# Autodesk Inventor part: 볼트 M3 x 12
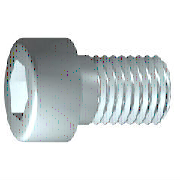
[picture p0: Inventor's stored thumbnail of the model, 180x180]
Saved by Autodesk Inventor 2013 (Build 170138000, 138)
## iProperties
IsCustomPart: 0
Created: 2012-02
Part Number: 볼트 M3 x 12
Material: 강철, 연강
Description: 6각머리 태핑 나사
Document SubType Name: Modeling
Standard: KS B 1003
Designer: mduedu
Standards Organization: KS
Language: ko-KR
Size Designation: M 3 x 12
Categories: <MemberInstance><Categories><Category DisplayName="조임쇠" InternalName="e4da775c-781d-43d5-af7c-5136215cf5a6" Mnemonic="FSTN"><Category DisplayName="볼트" InternalN
Density: 7.86 g/cm^3
Mass: 1.15208 g
Surface Area: 2.207 cm^2
Volume: 0.146575 cm^3
Author: mduedu
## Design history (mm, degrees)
sketch "스케치1"
  geometry: L1 (-0.867, 0)-(12, 0); L2 (12, 0)-(12, 1.5); L3 (12, 1.5)-(1.25, 1.5); L4 (1.25, 1.5)-(0.943, 1.5); L5 (0.943, 1.5)-(0, 1.5); L6 (0, 1.5)-(0, 2.75); L7 (0, 2.75)-(-3, 2.75); L8 (-3, 2.75)-(-3, 1.443); L9 (-3, 1.443)-(-1.7, 1.443); L10 (-1.7, 1.443)-(-0.867, 0); L11 (-6, 0)-(15, 0) reference; L12 (0, -0.55)-(0, 3.3) reference; L13 (1.25, 1.5)-(0, 1.5)
  constraints: 22 end point, 6 parallel, 2 collinear, 2 perpendicular, 1 horizontal, 1 point on line
  dimensions: "d1" = 10.75 distance from line of L3.end L2 (= GEL); "d2" = 0.30683 distance of L4.end L3.end (computed from GAL); "d3" = 3 distance between parallel lines of L8 L6 (= KOH); "d4" = 1.3 distance of L8.end L9.end (= INTI); "d5" = 60 deg angle of L10 L1; "d6" = 3 diameter of L3 L1 (= GD); "d7" = 3 diameter of L5 L1 (= BDM); "d8" = 2.88675 diameter of L9 L1 (= 1.1547 x SW); "d9" = 5.5 diameter of L7 L1 (= KOD); "d26" = 12 distance between parallel lines of L12 L2 (= NLG)
revolve "본체" sketch "스케치1" stored, may be unused: angle "d10" = 90 deg
sketch "스케치2"
  geometry: L1 (0, -3.85)-(0, 3.85) reference; L2 (-3.85, 0)-(3.85, 0) reference; L3 (1.443, 0)-(0.722, -1.25); L4 (0.722, -1.25)-(-0.722, -1.25); L5 (-0.722, -1.25)-(-1.443, 0); L6 (-1.443, 0)-(-0.722, 1.25); L7 (-0.722, 1.25)-(0.722, 1.25); L8 (0.722, 1.25)-(1.443, 0); 2 further points
  constraints: 12 end point, 1 coincident, 1 horizontal alignment, 1 point on line, 12 other
extrude "슬롯" join sketch "스케치2" stored distance "d11" = 10; taper "d12" = 0 deg
workplane "Work Plane1"
fillet "Fillet2" dims "d30" = 0.1 (= R)
body "Solid1"
fillet "모깎기1" dims "d17" = 0.3 (= RR)
feature "스레드" dims "d13" = 10.75 (= GEL), "d14" = 0
chamfer "모따기1" distance "d15" = 0.30673 (= -0.5 x SPD + 0.5 x GD); stored, may be unused: second distance "d16" = 0.30673 (= GUL), angle "d27" = 45 deg
other parameters: "GD" = 3 (= NND) [user parameter; used in 2 equation terms], "NLG" = 12 [user parameter; used in 1 equation term], "GEL" = 10.75 [user parameter; used in 2 equation terms], "KOD" = 5.5 [user parameter; used in 1 equation term], "KOH" = 3 [user parameter; used in 1 equation term], "INTI" = 1.3 [user parameter; used in 1 equation term], "GAL" = 0.30673 (= 0.61345 x PTC) [user parameter; used in 1 equation term], "GUL" = 0.30673 (= 0.61345 x PTC) [user parameter; used in 1 equation term], "BDM" = 3 (= NND) [user parameter; used in 1 equation term], "SW" = 2.5 [user parameter; used in 2 equation terms], "RR" = 0.3 [user parameter; used in 1 equation term], "SPD" = 2.38655 (= NND - 1.2269 x PTC) [user parameter; used in 1 equation term], "d19" = 0, "d28" = 0, "d29" = 0, "R" = 0.1 [user parameter; used in 1 equation term], "PHH" = 0.1 [user parameter], "GD1" = 2.38655 (= THREADDIA - 1.2269 x PTC) [user parameter], "THREADDIA" = 3 [user parameter; used in 1 equation term], "FAWI" = 45 deg [user parameter], "PTC" = 0.5 [user parameter; used in 5 equation terms], "NND" = 3 [user parameter; used in 3 equation terms], "TOA" = 30 deg [user parameter], "E0" = 2.8875 (= 1.155 x SW) [user parameter]
